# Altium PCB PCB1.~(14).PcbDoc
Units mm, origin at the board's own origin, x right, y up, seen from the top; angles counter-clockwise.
Board outline 149.35 x 57.4 mm, 2 copper layers (Top Layer, Bottom Layer); 100 components, 175 nets, 429 pads, 116 vias.
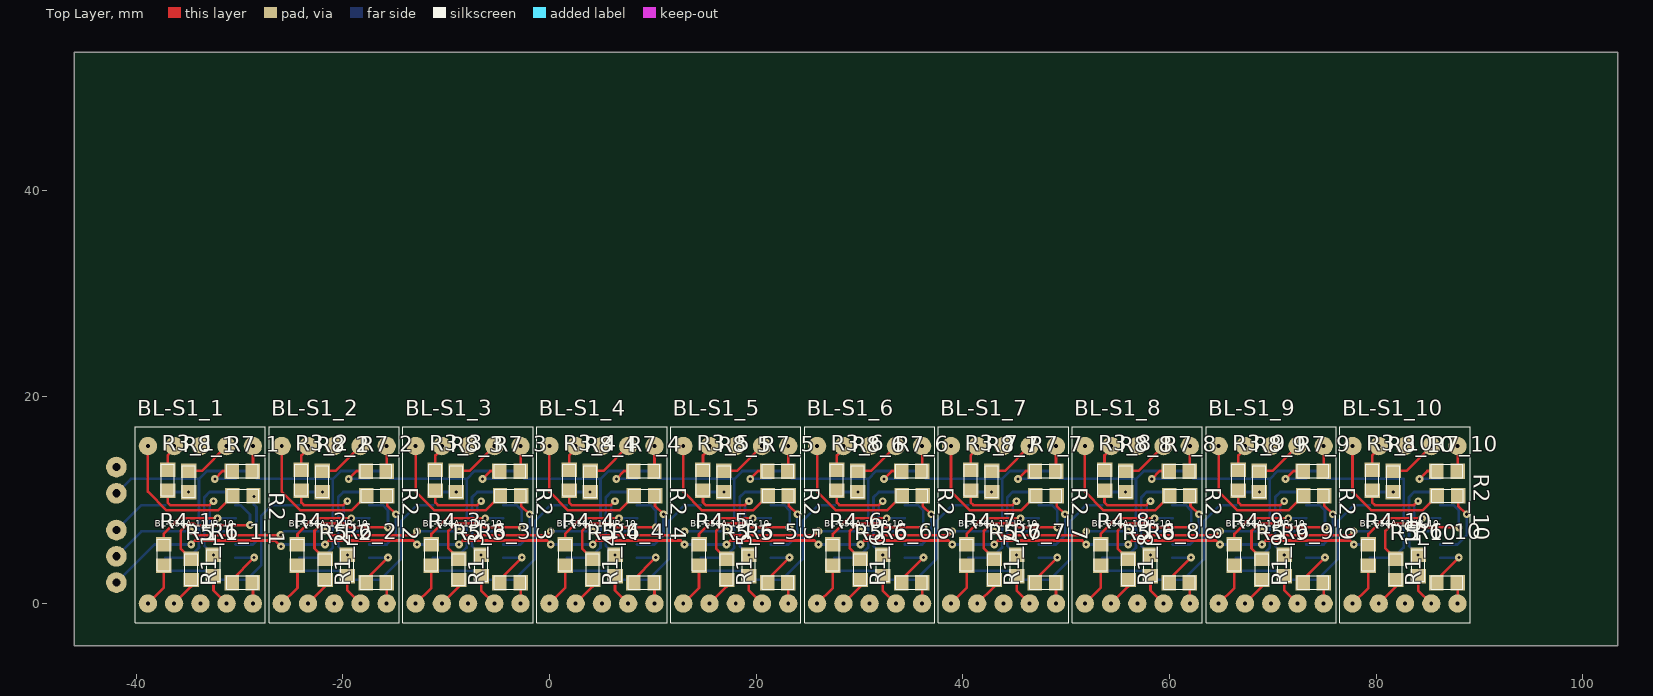
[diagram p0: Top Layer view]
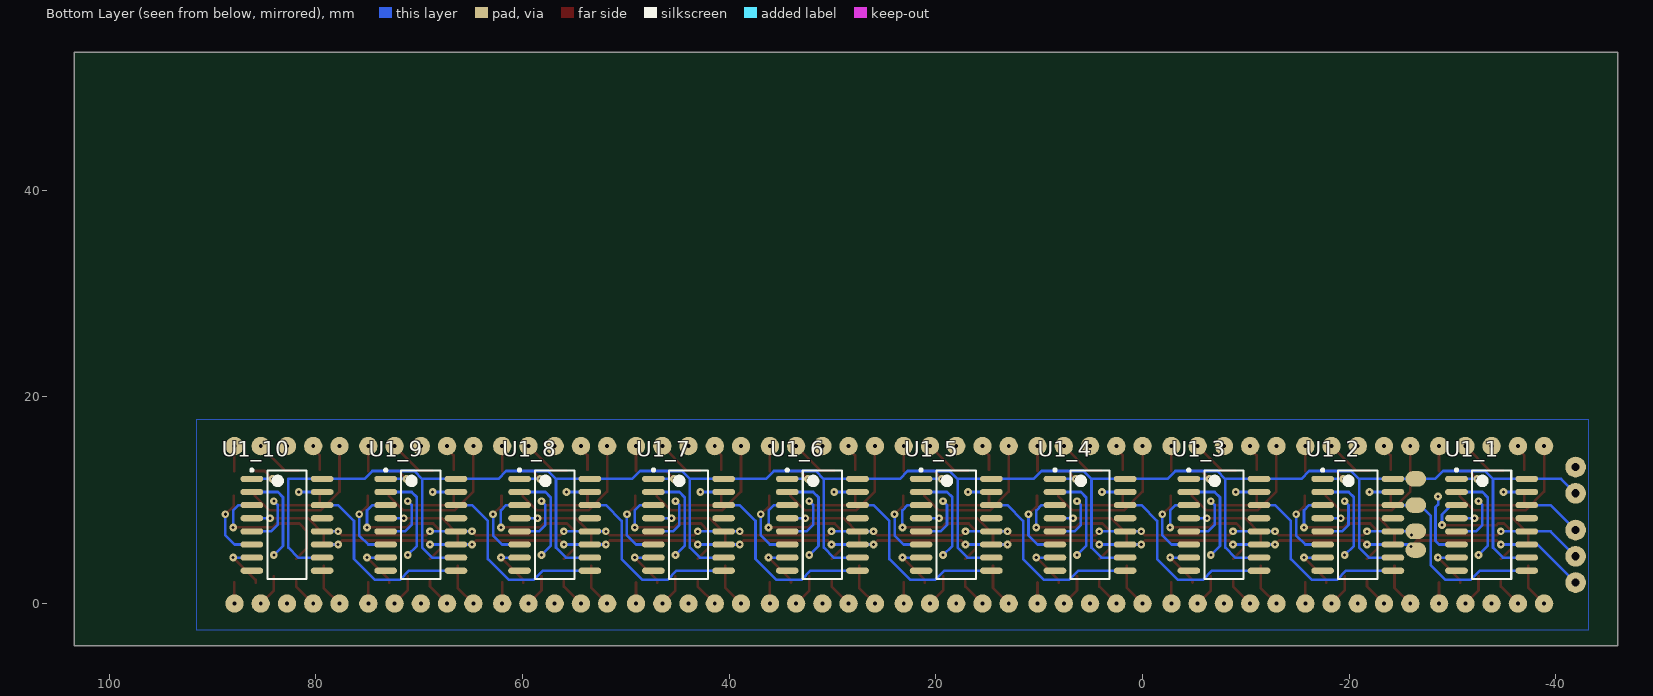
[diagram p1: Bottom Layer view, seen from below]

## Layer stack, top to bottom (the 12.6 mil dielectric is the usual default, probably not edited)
Top Solder: solder mask 0.0102, Solder Resist, Dk 3.5
Top Layer: signal copper 0.0356
Dielectric 1: dielectric 0.32, FR-4, Dk 4.8
Bottom Layer: signal copper 0.0356
Bottom Solder: solder mask 0.0102, Solder Resist, Dk 3.5

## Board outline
-45.974,-4.064 -45.974,53.34 103.378,53.34 103.378,-4.064 -5.588,-4.064

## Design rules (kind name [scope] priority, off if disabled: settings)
Clearance [All] p1: gap=0.127
MinimumSolderMaskSliver [All] p1 off: minsoldermaskwidth=0.254
PolygonConnect [All] p1: connectstyle=Relief reliefconductorwidth=0.254 reliefentries=4 polygonreliefangle="90 Angle" airgapwidth=0.381
RoomDefinition 10 [InComponentClass('10')] p1: confinementstyle=ConfineIn formatcopy=TRUE lockcomponents=FALSE outline 76.327,-2.54 91.44,-2.54 91.44,17.78 76.327,17.78
RoomDefinition 9 [InComponentClass('9')] p2: confinementstyle=ConfineIn formatcopy=TRUE lockcomponents=FALSE outline 63.373,-2.54 78.486,-2.54 78.486,17.78 63.373,17.78
RoomDefinition 8 [InComponentClass('8')] p3: confinementstyle=ConfineIn formatcopy=TRUE lockcomponents=FALSE outline 50.419,-2.54 65.532,-2.54 65.532,17.78 50.419,17.78
RoomDefinition 7 [InComponentClass('7')] p4: confinementstyle=ConfineIn formatcopy=TRUE lockcomponents=FALSE outline 37.465,-2.54 52.578,-2.54 52.578,17.78 37.465,17.78
RoomDefinition 6 [InComponentClass('6')] p5: confinementstyle=ConfineIn formatcopy=TRUE lockcomponents=FALSE outline 24.511,-2.54 39.624,-2.54 39.624,17.78 24.511,17.78
RoomDefinition 5 [InComponentClass('5')] p6: confinementstyle=ConfineIn formatcopy=TRUE lockcomponents=FALSE outline 11.557,-2.54 26.67,-2.54 26.67,17.78 11.557,17.78
RoomDefinition 4 [InComponentClass('4')] p7: confinementstyle=ConfineIn formatcopy=TRUE lockcomponents=FALSE outline -1.397,-2.54 13.716,-2.54 13.716,17.78 -1.397,17.78
RoomDefinition 2 [InComponentClass('2')] p8: confinementstyle=ConfineIn formatcopy=TRUE lockcomponents=FALSE outline -27.305,-2.54 -12.192,-2.54 -12.192,17.78 -27.305,17.78
RoomDefinition 1 [InComponentClass('1')] p9: confinementstyle=ConfineIn formatcopy=TRUE lockcomponents=FALSE outline -40.259,-2.54 -25.146,-2.54 -25.146,17.78 -40.259,17.78
RoomDefinition 3 [InComponentClass('3')] p10: confinementstyle=ConfineIn formatcopy=TRUE lockcomponents=FALSE outline -14.351,-2.54 0.762,-2.54 0.762,17.78 -14.351,17.78
RoutingVias [All] p1: holewidth=0.3 width=0.75 viastyle="Through Hole" minholewidth=0.3 minwidth=0.75 maxholewidth=0.711 maxwidth=1.778
SilkToBoardRegionClearance [All] p1 off:
SilkToSilkClearance [All] p1 off: silktosilkclearance=0.254
SilkToSolderMaskClearance [IsPad] p1 off: minsilkscreentomaskgap=0.254 clearancetoexposedcopper=TRUE
SolderMaskExpansion [All] p1: expansion=0.102
Width [All] p1: maxlimit=0.254 minlimit=0.2 preferedwidth=0.254
26 further rules are at their usual default settings.

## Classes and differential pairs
component class 6: BL-S1_6 R1_6 R2_6 R3_6 R4_6 R5_6 R6_6 R7_6 R8_6 U1_6
component class 5: BL-S1_5 R1_5 R2_5 R3_5 R4_5 R5_5 R6_5 R7_5 R8_5 U1_5
component class 1: BL-S1_1 R1_1 R2_1 R3_1 R4_1 R5_1 R6_1 R7_1 R8_1 U1_1
component class 2: BL-S1_2 R1_2 R2_2 R3_2 R4_2 R5_2 R6_2 R7_2 R8_2 U1_2
component class 3: BL-S1_3 R1_3 R2_3 R3_3 R4_3 R5_3 R6_3 R7_3 R8_3 U1_3
component class 4: BL-S1_4 R1_4 R2_4 R3_4 R4_4 R5_4 R6_4 R7_4 R8_4 U1_4
channel class Sheet2: 1 2 3 4 5 6 7 8 9 10
component class 7: BL-S1_7 R1_7 R2_7 R3_7 R4_7 R5_7 R6_7 R7_7 R8_7 U1_7
component class 8: BL-S1_8 R1_8 R2_8 R3_8 R4_8 R5_8 R6_8 R7_8 R8_8 U1_8
component class 9: BL-S1_9 R1_9 R2_9 R3_9 R4_9 R5_9 R6_9 R7_9 R8_9 U1_9
component class 10: BL-S1_10 R1_10 R2_10 R3_10 R4_10 R5_10 R6_10 R7_10 R8_10 U1_10

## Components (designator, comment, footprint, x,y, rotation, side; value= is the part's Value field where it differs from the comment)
BL-S1_1 "BL-S56A-11UR" BL-S56A-11UR -40.082,7.62 r0 top locked (schematic designator BL-S1)
BL-S1_2 "BL-S56A-11UR" BL-S56A-11UR -27.128,7.62 r0 top (schematic designator BL-S1)
BL-S1_3 "BL-S56A-11UR" BL-S56A-11UR -14.174,7.62 r0 top (schematic designator BL-S1)
BL-S1_4 "BL-S56A-11UR" BL-S56A-11UR -1.22,7.62 r0 top (schematic designator BL-S1)
BL-S1_5 "BL-S56A-11UR" BL-S56A-11UR 11.734,7.62 r0 top (schematic designator BL-S1)
BL-S1_6 "BL-S56A-11UR" BL-S56A-11UR 24.688,7.62 r0 top (schematic designator BL-S1)
BL-S1_7 "BL-S56A-11UR" BL-S56A-11UR 37.642,7.62 r0 top (schematic designator BL-S1)
BL-S1_8 "BL-S56A-11UR" BL-S56A-11UR 50.596,7.62 r0 top (schematic designator BL-S1)
BL-S1_9 "BL-S56A-11UR" BL-S56A-11UR 63.55,7.62 r0 top (schematic designator BL-S1)
BL-S1_10 "BL-S56A-11UR" BL-S56A-11UR 76.504,7.62 r0 top (schematic designator BL-S1)
R1_1 "310R" Res0805 -29.718,2.032 r180 top (schematic designator R1)
R1_2 "310R" Res0805 -16.764,2.032 r180 top (schematic designator R1)
R1_3 "310R" Res0805 -3.81,2.032 r180 top (schematic designator R1)
R1_4 "310R" Res0805 9.144,2.032 r180 top (schematic designator R1)
R1_5 "310R" Res0805 22.098,2.032 r180 top (schematic designator R1)
R1_6 "310R" Res0805 35.052,2.032 r180 top (schematic designator R1)
R1_7 "310R" Res0805 48.006,2.032 r180 top (schematic designator R1)
R1_8 "310R" Res0805 60.96,2.032 r180 top (schematic designator R1)
R1_9 "310R" Res0805 73.914,2.032 r180 top (schematic designator R1)
R1_10 "310R" Res0805 86.868,2.032 r180 top (schematic designator R1)
R2_1 "310R" Res0805 -29.666,10.414 r0 top (schematic designator R2)
R2_2 "310R" Res0805 -16.712,10.414 r0 top (schematic designator R2)
R2_3 "310R" Res0805 -3.758,10.414 r0 top (schematic designator R2)
R2_4 "310R" Res0805 9.196,10.414 r0 top (schematic designator R2)
R2_5 "310R" Res0805 22.15,10.414 r0 top (schematic designator R2)
R2_6 "310R" Res0805 35.104,10.414 r0 top (schematic designator R2)
R2_7 "310R" Res0805 48.058,10.414 r0 top (schematic designator R2)
R2_8 "310R" Res0805 61.012,10.414 r0 top (schematic designator R2)
R2_9 "310R" Res0805 73.966,10.414 r0 top (schematic designator R2)
R2_10 "310R" Res0805 86.92,10.414 r0 top (schematic designator R2)
R3_1 "310R" Res0805 -36.957,11.938 r270 top (schematic designator R3)
R3_2 "310R" Res0805 -24.003,11.938 r270 top (schematic designator R3)
R3_3 "310R" Res0805 -11.049,11.938 r270 top (schematic designator R3)
R3_4 "310R" Res0805 1.905,11.938 r270 top (schematic designator R3)
R3_5 "310R" Res0805 14.859,11.938 r270 top (schematic designator R3)
R3_6 "310R" Res0805 27.813,11.938 r270 top (schematic designator R3)
R3_7 "310R" Res0805 40.767,11.938 r270 top (schematic designator R3)
R3_8 "310R" Res0805 53.721,11.938 r270 top (schematic designator R3)
R3_9 "310R" Res0805 66.675,11.938 r270 top (schematic designator R3)
R3_10 "310R" Res0805 79.629,11.938 r270 top (schematic designator R3)
R4_1 "310R" Res0805 -37.338,4.699 r90 top (schematic designator R4)
R4_2 "310R" Res0805 -24.384,4.699 r90 top (schematic designator R4)
R4_3 "310R" Res0805 -11.43,4.699 r90 top (schematic designator R4)
R4_4 "310R" Res0805 1.524,4.699 r90 top (schematic designator R4)
R4_5 "310R" Res0805 14.478,4.699 r90 top (schematic designator R4)
R4_6 "310R" Res0805 27.432,4.699 r90 top (schematic designator R4)
R4_7 "310R" Res0805 40.386,4.699 r90 top (schematic designator R4)
R4_8 "310R" Res0805 53.34,4.699 r90 top (schematic designator R4)
R4_9 "310R" Res0805 66.294,4.699 r90 top (schematic designator R4)
R4_10 "310R" Res0805 79.248,4.699 r90 top (schematic designator R4)
R5_1 "310R" Res0805 -34.671,3.302 r90 top (schematic designator R5)
R5_2 "310R" Res0805 -21.717,3.302 r90 top (schematic designator R5)
R5_3 "310R" Res0805 -8.763,3.302 r90 top (schematic designator R5)
R5_4 "310R" Res0805 4.191,3.302 r90 top (schematic designator R5)
R5_5 "310R" Res0805 17.145,3.302 r90 top (schematic designator R5)
R5_6 "310R" Res0805 30.099,3.302 r90 top (schematic designator R5)
R5_7 "310R" Res0805 43.053,3.302 r90 top (schematic designator R5)
R5_8 "310R" Res0805 56.007,3.302 r90 top (schematic designator R5)
R5_9 "310R" Res0805 68.961,3.302 r90 top (schematic designator R5)
R5_10 "310R" Res0805 81.915,3.302 r90 top (schematic designator R5)
R6_1 "310R" Res0805 -32.512,3.683 r90 top (schematic designator R6)
R6_2 "310R" Res0805 -19.558,3.683 r90 top (schematic designator R6)
R6_3 "310R" Res0805 -6.604,3.683 r90 top (schematic designator R6)
R6_4 "310R" Res0805 6.35,3.683 r90 top (schematic designator R6)
R6_5 "310R" Res0805 19.304,3.683 r90 top (schematic designator R6)
R6_6 "310R" Res0805 32.258,3.683 r90 top (schematic designator R6)
R6_7 "310R" Res0805 45.212,3.683 r90 top (schematic designator R6)
R6_8 "310R" Res0805 58.166,3.683 r90 top (schematic designator R6)
R6_9 "310R" Res0805 71.12,3.683 r90 top (schematic designator R6)
R6_10 "310R" Res0805 84.074,3.683 r90 top (schematic designator R6)
R7_1 "310R" Res0805 -29.718,12.827 r180 top (schematic designator R7)
R7_2 "310R" Res0805 -16.764,12.827 r180 top (schematic designator R7)
R7_3 "310R" Res0805 -3.81,12.827 r180 top (schematic designator R7)
R7_4 "310R" Res0805 9.144,12.827 r180 top (schematic designator R7)
R7_5 "310R" Res0805 22.098,12.827 r180 top (schematic designator R7)
R7_6 "310R" Res0805 35.052,12.827 r180 top (schematic designator R7)
R7_7 "310R" Res0805 48.006,12.827 r180 top (schematic designator R7)
R7_8 "310R" Res0805 60.96,12.827 r180 top (schematic designator R7)
R7_9 "310R" Res0805 73.914,12.827 r180 top (schematic designator R7)
R7_10 "310R" Res0805 86.868,12.827 r180 top (schematic designator R7)
R8_1 "310R" Res0805 -34.925,11.811 r270 top (schematic designator R8)
R8_2 "310R" Res0805 -21.971,11.811 r270 top (schematic designator R8)
R8_3 "310R" Res0805 -9.017,11.811 r270 top (schematic designator R8)
R8_4 "310R" Res0805 3.937,11.811 r270 top (schematic designator R8)
R8_5 "310R" Res0805 16.891,11.811 r270 top (schematic designator R8)
R8_6 "310R" Res0805 29.845,11.811 r270 top (schematic designator R8)
R8_7 "310R" Res0805 42.799,11.811 r270 top (schematic designator R8)
R8_8 "310R" Res0805 55.753,11.811 r270 top (schematic designator R8)
R8_9 "310R" Res0805 68.707,11.811 r270 top (schematic designator R8)
R8_10 "310R" Res0805 81.661,11.811 r270 top (schematic designator R8)
U1_1 "HD74HC595FP" PRSP0016DH-B_N -33.782,7.62 r180 bottom (schematic designator U1)
U1_2 "HD74HC595FP" PRSP0016DH-B_N -20.828,7.62 r180 bottom (schematic designator U1)
U1_3 "HD74HC595FP" PRSP0016DH-B_N -7.874,7.62 r180 bottom (schematic designator U1)
U1_4 "HD74HC595FP" PRSP0016DH-B_N 5.08,7.62 r180 bottom (schematic designator U1)
U1_5 "HD74HC595FP" PRSP0016DH-B_N 18.034,7.62 r180 bottom (schematic designator U1)
U1_6 "HD74HC595FP" PRSP0016DH-B_N 30.988,7.62 r180 bottom (schematic designator U1)
U1_7 "HD74HC595FP" PRSP0016DH-B_N 43.942,7.62 r180 bottom (schematic designator U1)
U1_8 "HD74HC595FP" PRSP0016DH-B_N 56.896,7.62 r180 bottom (schematic designator U1)
U1_9 "HD74HC595FP" PRSP0016DH-B_N 69.85,7.62 r180 bottom (schematic designator U1)
U1_10 "HD74HC595FP" PRSP0016DH-B_N 82.804,7.62 r180 bottom (schematic designator U1)

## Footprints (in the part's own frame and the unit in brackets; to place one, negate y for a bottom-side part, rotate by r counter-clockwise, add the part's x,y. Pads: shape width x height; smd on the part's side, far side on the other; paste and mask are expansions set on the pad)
BL-S56A-11UR [mil]
  round 70 hole 15: 1(48.03,-300) 2(148.03,-300) 3(248.03,-300) 4(348.03,-300) 5(448.03,-300) 6(448.03,300) 7(348.03,300) 8(248.03,300) 9(148.03,300) 10(48.03,300)
  silkscreen extent 0,-374 496,374, body extent 0,-374 496,374, height 315
PRSP0016DH-B_N [mm] "SOP, 16-Leads, Body 10.06x5.5mm, Pitch 1.27mm, IPC Medium Density"
  oval 2.2x0.6 smd: 1(-3.4,4.445) 2(-3.4,3.175) 3(-3.4,1.905) 4(-3.4,0.635) 5(-3.4,-0.635) 6(-3.4,-1.905) 7(-3.4,-3.175) 8(-3.4,-4.445) 9(3.4,-4.445) 10(3.4,-3.175) 11(3.4,-1.905) 12(3.4,-0.635) 13(3.4,0.635) 14(3.4,1.905) 15(3.4,3.175) 16(3.4,4.445)
  silkscreen extent -3.52,-5.25 1.9,5.42, body extent -2.7,-5.25 2.7,5.25, height 2.2
Res0805 [mm]
  rect 1.4x1.5 smd: 1(-1.025,0) 2(1.025,0)
  silkscreen extent -1.52,-0.64 1.52,0.64, body extent -1.15,-0.67 1.15,0.68, height 0.76

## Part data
BL-S1_1 BL-S1_2 BL-S1_3 BL-S1_4 BL-S1_5 BL-S1_6 BL-S1_7 BL-S1_8 BL-S1_9 BL-S1_10: library part Component_1
R1_1 R1_2 R1_3 R1_4 R1_5 R1_6 R1_7 R1_8 R1_9 R1_10 R2_1 R2_2 R2_3 R2_4 R2_5 R2_6 R2_7 R2_8 R2_9 R2_10 R3_1 R3_2 R3_3 R3_4 R3_5 R3_6 R3_7 R3_8 R3_9 R3_10 R4_1 R4_2 R4_3 R4_4 R4_5 R4_6 R4_7 R4_8 R4_9 R4_10 R5_1 R5_2 R5_3 R5_4 R5_5 R5_6 R5_7 R5_8 R5_9 R5_10 R6_1 R6_2 R6_3 R6_4 R6_5 R6_6 R6_7 R6_8 R6_9 R6_10 R7_1 R7_2 R7_3 R7_4 R7_5 R7_6 R7_7 R7_8 R7_9 R7_10 R8_1 R8_2 R8_3 R8_4 R8_5 R8_6 R8_7 R8_8 R8_9 R8_10: library part Res1, "Resistor"
U1_1 U1_2 U1_3 U1_4 U1_5 U1_6 U1_7 U1_8 U1_9 U1_10: "8-bit Shift Register / Latch with 3-State Outputs"

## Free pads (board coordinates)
  round 2 hole 0.8: 2(-41.91,4.572) 3(-41.91,2.032) 4(-41.91,7.112) 5(-41.91,10.668) 6(-41.91,13.208)
  oval 2x1.5 smd far side: 8(-26.44,12.065) 9(-26.44,9.525) 10(-26.44,6.985) 11(-26.441,5.182)

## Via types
v1: diameter 0.75, hole 0.3, Top Layer to Bottom Layer, tented both sides, 94 vias
v2: diameter 0.75, hole 0.3, Top Layer to Bottom Layer, 22 vias

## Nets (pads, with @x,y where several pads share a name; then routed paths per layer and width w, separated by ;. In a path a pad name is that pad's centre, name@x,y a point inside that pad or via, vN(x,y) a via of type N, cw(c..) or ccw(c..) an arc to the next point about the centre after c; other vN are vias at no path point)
+5V: pad.5 pad.8 U1_1.10 U1_1.16 U1_2.10 U1_2.16 U1_3.10 U1_3.16 U1_4.10 U1_4.16 U1_5.10 U1_5.16 U1_6.10 U1_6.16 U1_7.10 U1_7.16 U1_8.10 U1_8.16 U1_9.10 U1_9.16 U1_10.10 U1_10.16 | length 234.1
  Bottom Layer w0.254: pad.5 -40.513,12.065 U1_1.16 -33.909,12.065 -33.147,12.827 -29.083,12.827 -28.321,12.065 U1_2.16 -20.955,12.065 -20.193,12.827 -16.129,12.827 -15.367,12.065 U1_3.16 -8.001,12.065 -7.239,12.827 -3.175,12.827 -2.413,12.065 U1_4.16 4.947,12.065 ; U1_1.10 -34.872,4.445 -33.915,5.402 -33.915,12.065 ; U1_2.10 -21.918,4.445 -20.961,5.402 -20.961,12.065 ; U1_3.10 -8.964,4.445 -8.007,5.402 -8.007,12.065 ; U1_4.10 3.99,4.445 4.947,5.402 4.947,12.065 ; U1_5.10 16.944,4.445 17.901,5.402 17.901,12.065 ; U1_6.10 29.898,4.445 30.855,5.402 30.855,12.065 ; U1_7.10 42.852,4.445 43.809,5.402 43.809,12.065 ; U1_8.10 55.806,4.445 56.763,5.402 56.763,12.065 ; U1_9.10 68.76,4.445 69.717,5.402 69.717,12.065 ; U1_10.10 81.714,4.445 82.671,5.402 82.671,12.065 ; 82.677,12.065 82.671,12.065 ; 4.947,12.065 4.953,12.065 5.715,12.827 9.779,12.827 10.541,12.065 U1_5.16 17.901,12.065 ; 17.901,12.065 17.907,12.065 18.669,12.827 22.733,12.827 23.495,12.065 U1_6.16 30.855,12.065 ; 30.855,12.065 30.861,12.065 31.623,12.827 35.687,12.827 36.449,12.065 U1_7.16 43.809,12.065 ; 43.809,12.065 43.815,12.065 44.577,12.827 48.641,12.827 49.403,12.065 U1_8.16 56.763,12.065 ; 56.763,12.065 56.769,12.065 57.531,12.827 61.595,12.827 62.357,12.065 U1_9.16 69.717,12.065 ; 69.717,12.065 69.723,12.065 70.485,12.827 74.549,12.827 75.311,12.065 U1_10.16 82.671,12.065
GND: BL-S1_1.3 BL-S1_1.8 BL-S1_2.3 BL-S1_2.8 BL-S1_3.3 BL-S1_3.8 BL-S1_4.3 BL-S1_4.8 BL-S1_5.3 BL-S1_5.8 BL-S1_6.3 BL-S1_6.8 BL-S1_7.3 BL-S1_7.8 BL-S1_8.3 BL-S1_8.8 BL-S1_9.3 BL-S1_9.8 BL-S1_10.3 BL-S1_10.8 pad.6 U1_1.8 U1_1.13 U1_2.8 U1_2.13 U1_3.8 U1_3.13 U1_4.8 U1_4.13 U1_5.8 U1_5.13 U1_6.8 U1_6.13 U1_7.8 U1_7.13 U1_8.8 U1_8.13 U1_9.8 U1_9.13 U1_10.8 U1_10.13
L_A_1: BL-S1_1.7 R8_1.1 | length 4.7
  Top Layer w0.254: R8_1.1 -33.646,12.836 BL-S1_1.7
L_A_2: BL-S1_2.7 R8_2.1 | length 4.7
  Top Layer w0.254: R8_2.1 -20.692,12.836 BL-S1_2.7
L_A_3: BL-S1_3.7 R8_3.1 | length 4.7
  Top Layer w0.254: R8_3.1 -7.738,12.836 BL-S1_3.7
L_A_4: BL-S1_4.7 R8_4.1 | length 4.7
  Top Layer w0.254: R8_4.1 5.216,12.836 BL-S1_4.7
L_A_5: BL-S1_5.7 R8_5.1 | length 4.7
  Top Layer w0.254: R8_5.1 18.17,12.836 BL-S1_5.7
L_A_6: BL-S1_6.7 R8_6.1 | length 9.4
  Top Layer w0.254: 31.124,12.836 R8_6.1 31.124,12.836 ; 31.124,12.836 BL-S1_6.7 31.124,12.836
L_A_7: BL-S1_7.7 R8_7.1 | length 4.7
  Top Layer w0.254: R8_7.1 44.078,12.836 BL-S1_7.7
L_A_8: BL-S1_8.7 R8_8.1 | length 4.7
  Top Layer w0.254: R8_8.1 57.032,12.836 BL-S1_8.7
L_A_9: BL-S1_9.7 R8_9.1 | length 4.7
  Top Layer w0.254: R8_9.1 69.986,12.836 BL-S1_9.7
L_A_10: BL-S1_10.7 R8_10.1 | length 4.7
  Top Layer w0.254: R8_10.1 82.94,12.836 BL-S1_10.7
L_B_1: BL-S1_1.6 R7_1.1 | length 2.4
  Top Layer w0.254: BL-S1_1.6 -28.693,15.231 R7_1.1
L_B_2: BL-S1_2.6 R7_2.1 | length 2.4
  Top Layer w0.254: BL-S1_2.6 -15.739,15.231 R7_2.1
L_B_3: BL-S1_3.6 R7_3.1 | length 2.4
  Top Layer w0.254: BL-S1_3.6 -2.785,15.231 R7_3.1
L_B_4: BL-S1_4.6 R7_4.1 | length 2.4
  Top Layer w0.254: BL-S1_4.6 10.169,15.231 R7_4.1
L_B_5: BL-S1_5.6 R7_5.1 | length 2.4
  Top Layer w0.254: BL-S1_5.6 23.123,15.231 R7_5.1
L_B_6: BL-S1_6.6 R7_6.1 | length 4.8
  Top Layer w0.254: BL-S1_6.6@36.077,15.231 R7_6.1 BL-S1_6.6@36.077,15.231 ; BL-S1_6.6@36.077,15.231 BL-S1_6.6 BL-S1_6.6@36.077,15.231
L_B_7: BL-S1_7.6 R7_7.1 | length 2.4
  Top Layer w0.254: BL-S1_7.6 49.031,15.231 R7_7.1
L_B_8: BL-S1_8.6 R7_8.1 | length 2.4
  Top Layer w0.254: BL-S1_8.6 61.985,15.231 R7_8.1
L_B_9: BL-S1_9.6 R7_9.1 | length 2.4
  Top Layer w0.254: BL-S1_9.6 74.939,15.231 R7_9.1
L_B_10: BL-S1_10.6 R7_10.1 | length 2.4
  Top Layer w0.254: BL-S1_10.6 87.893,15.231 R7_10.1
L_C_1: BL-S1_1.4 R6_1.1 | length 3.2
  Top Layer w0.254: R6_1.1 -32.512,1.27 BL-S1_1.4
L_C_2: BL-S1_2.4 R6_2.1 | length 3.2
  Top Layer w0.254: R6_2.1 -19.558,1.27 BL-S1_2.4
L_C_3: BL-S1_3.4 R6_3.1 | length 3.2
  Top Layer w0.254: R6_3.1 -6.604,1.27 BL-S1_3.4
L_C_4: BL-S1_4.4 R6_4.1 | length 3.2
  Top Layer w0.254: R6_4.1 6.35,1.27 BL-S1_4.4
L_C_5: BL-S1_5.4 R6_5.1 | length 3.2
  Top Layer w0.254: R6_5.1 19.304,1.27 BL-S1_5.4
L_C_6: BL-S1_6.4 R6_6.1 | length 6.4
  Top Layer w0.254: 32.258,1.27 R6_6.1 32.258,1.27 ; 32.258,1.27 BL-S1_6.4 32.258,1.27
L_C_7: BL-S1_7.4 R6_7.1 | length 3.2
  Top Layer w0.254: R6_7.1 45.212,1.27 BL-S1_7.4
L_C_8: BL-S1_8.4 R6_8.1 | length 3.2
  Top Layer w0.254: R6_8.1 58.166,1.27 BL-S1_8.4
L_C_9: BL-S1_9.4 R6_9.1 | length 3.2
  Top Layer w0.254: R6_9.1 71.12,1.27 BL-S1_9.4
L_C_10: BL-S1_10.4 R6_10.1 | length 3.2
  Top Layer w0.254: R6_10.1 84.074,1.27 BL-S1_10.4
L_D_1: BL-S1_1.2 R5_1.1 | length 2.8
  Top Layer w0.254: BL-S1_1.2 -34.671,1.651 R5_1.1@-34.671,2.15
L_D_2: BL-S1_2.2 R5_2.1 | length 2.8
  Top Layer w0.254: BL-S1_2.2 -21.717,1.651 R5_2.1@-21.717,2.15
L_D_3: BL-S1_3.2 R5_3.1 | length 2.8
  Top Layer w0.254: BL-S1_3.2 -8.763,1.651 R5_3.1@-8.763,2.15
L_D_4: BL-S1_4.2 R5_4.1 | length 2.8
  Top Layer w0.254: BL-S1_4.2 4.191,1.651 R5_4.1@4.191,2.15
L_D_5: BL-S1_5.2 R5_5.1 | length 2.8
  Top Layer w0.254: BL-S1_5.2 17.145,1.651 R5_5.1@17.145,2.15
L_D_6: BL-S1_6.2 R5_6.1 | length 5.7
  Top Layer w0.254: R5_6.1@30.099,1.651 BL-S1_6.2 R5_6.1@30.099,1.651 ; R5_6.1@30.099,1.651 30.099,2.15 R5_6.1@30.099,1.651
L_D_7: BL-S1_7.2 R5_7.1 | length 2.8
  Top Layer w0.254: BL-S1_7.2 43.053,1.651 R5_7.1@43.053,2.15
L_D_8: BL-S1_8.2 R5_8.1 | length 2.8
  Top Layer w0.254: BL-S1_8.2 56.007,1.651 R5_8.1@56.007,2.15
L_D_9: BL-S1_9.2 R5_9.1 | length 2.8
  Top Layer w0.254: BL-S1_9.2 68.961,1.651 R5_9.1@68.961,2.15
L_D_10: BL-S1_10.2 R5_10.1 | length 2.8
  Top Layer w0.254: BL-S1_10.2 81.915,1.651 R5_10.1@81.915,2.15
L_E_1: BL-S1_1.1 R4_1.1 | length 4.3
  Top Layer w0.254: BL-S1_1.1 -37.338,1.524 R4_1.1
L_E_2: BL-S1_2.1 R4_2.1 | length 4.3
  Top Layer w0.254: BL-S1_2.1 -24.384,1.524 R4_2.1
L_E_3: BL-S1_3.1 R4_3.1 | length 4.3
  Top Layer w0.254: BL-S1_3.1 -11.43,1.524 R4_3.1
L_E_4: BL-S1_4.1 R4_4.1 | length 4.3
  Top Layer w0.254: BL-S1_4.1 1.524,1.524 R4_4.1
L_E_5: BL-S1_5.1 R4_5.1 | length 4.3
  Top Layer w0.254: BL-S1_5.1 14.478,1.524 R4_5.1
L_E_6: BL-S1_6.1 R4_6.1 | length 8.6
  Top Layer w0.254: 27.432,1.524 BL-S1_6.1 27.432,1.524 ; 27.432,1.524 R4_6.1 27.432,1.524
L_E_7: BL-S1_7.1 R4_7.1 | length 4.3
  Top Layer w0.254: BL-S1_7.1 40.386,1.524 R4_7.1
L_E_8: BL-S1_8.1 R4_8.1 | length 4.3
  Top Layer w0.254: BL-S1_8.1 53.34,1.524 R4_8.1
L_E_9: BL-S1_9.1 R4_9.1 | length 4.3
  Top Layer w0.254: BL-S1_9.1 66.294,1.524 R4_9.1
L_E_10: BL-S1_10.1 R4_10.1 | length 4.3
  Top Layer w0.254: BL-S1_10.1 79.248,1.524 R4_10.1
L_F_1: BL-S1_1.9 R3_1.1 | length 2.5
  Top Layer w0.254: R3_1.1 -36.957,14.351 -36.322,14.986 BL-S1_1.9
L_F_2: BL-S1_2.9 R3_2.1 | length 2.5
  Top Layer w0.254: R3_2.1 -24.003,14.351 -23.368,14.986 BL-S1_2.9
L_F_3: BL-S1_3.9 R3_3.1 | length 2.5
  Top Layer w0.254: R3_3.1 -11.049,14.351 -10.414,14.986 BL-S1_3.9
L_F_4: BL-S1_4.9 R3_4.1 | length 2.5
  Top Layer w0.254: R3_4.1 1.905,14.351 2.54,14.986 BL-S1_4.9
L_F_5: BL-S1_5.9 R3_5.1 | length 2.5
  Top Layer w0.254: R3_5.1 14.859,14.351 15.494,14.986 BL-S1_5.9
L_F_6: BL-S1_6.9 R3_6.1 | length 5.1
  Top Layer w0.254: 27.813,14.351 R3_6.1 27.813,14.351 ; 27.813,14.351 BL-S1_6.9@28.448,14.986 ; 27.813,14.351 BL-S1_6.9@28.448,14.986 ; BL-S1_6.9@28.448,14.986 BL-S1_6.9 BL-S1_6.9@28.448,14.986
L_F_7: BL-S1_7.9 R3_7.1 | length 2.5
  Top Layer w0.254: R3_7.1 40.767,14.351 41.402,14.986 BL-S1_7.9
L_F_8: BL-S1_8.9 R3_8.1 | length 2.5
  Top Layer w0.254: R3_8.1 53.721,14.351 54.356,14.986 BL-S1_8.9
L_F_9: BL-S1_9.9 R3_9.1 | length 2.5
  Top Layer w0.254: R3_9.1 66.675,14.351 67.31,14.986 BL-S1_9.9
L_F_10: BL-S1_10.9 R3_10.1 | length 2.5
  Top Layer w0.254: R3_10.1 79.629,14.351 80.264,14.986 BL-S1_10.9
L_G_1: BL-S1_1.10 R2_1.1 | length 13.9
  Top Layer w0.254: BL-S1_1.10 -38.862,10.829 -37.044,9.011 -32.094,9.011 R2_1.1
L_G_2: BL-S1_2.10 R2_2.1 | length 13.9
  Top Layer w0.254: BL-S1_2.10 -25.908,10.829 -24.09,9.011 -19.14,9.011 R2_2.1
L_G_3: BL-S1_3.10 R2_3.1 | length 13.9
  Top Layer w0.254: BL-S1_3.10 -12.954,10.829 -11.136,9.011 -6.186,9.011 R2_3.1
L_G_4: BL-S1_4.10 R2_4.1 | length 13.9
  Top Layer w0.254: BL-S1_4.10 0,10.829 1.818,9.011 6.768,9.011 R2_4.1
L_G_5: BL-S1_5.10 R2_5.1 | length 13.9
  Top Layer w0.254: BL-S1_5.10 12.954,10.829 14.772,9.011 19.722,9.011 R2_5.1
L_G_6: BL-S1_6.10 R2_6.1 | length 27.8
  Top Layer w0.254: 25.908,10.829 27.726,9.011 ; 25.908,10.829 BL-S1_6.10 25.908,10.829 ; 25.908,10.829 27.726,9.011 ; 27.726,9.011 32.676,9.011 ; 27.726,9.011 32.676,9.011 ; 32.676,9.011 R2_6.1 32.676,9.011
L_G_7: BL-S1_7.10 R2_7.1 | length 13.9
  Top Layer w0.254: BL-S1_7.10 38.862,10.829 40.68,9.011 45.63,9.011 R2_7.1
L_G_8: BL-S1_8.10 R2_8.1 | length 13.9
  Top Layer w0.254: BL-S1_8.10 51.816,10.829 53.634,9.011 58.584,9.011 R2_8.1
L_G_9: BL-S1_9.10 R2_9.1 | length 13.9
  Top Layer w0.254: BL-S1_9.10 64.77,10.829 66.588,9.011 71.538,9.011 R2_9.1
L_G_10: BL-S1_10.10 R2_10.1 | length 13.9
  Top Layer w0.254: BL-S1_10.10 77.724,10.829 79.542,9.011 84.492,9.011 R2_10.1
L_H_1: BL-S1_1.5 R1_1.1 | length 2
  Top Layer w0.254: BL-S1_1.5 -28.693,0.009 R1_1.1
L_H_2: BL-S1_2.5 R1_2.1 | length 2
  Top Layer w0.254: BL-S1_2.5 -15.739,0.009 R1_2.1
L_H_3: BL-S1_3.5 R1_3.1 | length 2
  Top Layer w0.254: BL-S1_3.5 -2.785,0.009 R1_3.1
L_H_4: BL-S1_4.5 R1_4.1 | length 2
  Top Layer w0.254: BL-S1_4.5 10.169,0.009 R1_4.1
L_H_5: BL-S1_5.5 R1_5.1 | length 2
  Top Layer w0.254: BL-S1_5.5 23.123,0.009 R1_5.1
L_H_6: BL-S1_6.5 R1_6.1 | length 4.1
  Top Layer w0.254: BL-S1_6.5@36.077,0.009 BL-S1_6.5 BL-S1_6.5@36.077,0.009 ; BL-S1_6.5@36.077,0.009 R1_6.1 BL-S1_6.5@36.077,0.009
L_H_7: BL-S1_7.5 R1_7.1 | length 2
  Top Layer w0.254: BL-S1_7.5 49.031,0.009 R1_7.1
L_H_8: BL-S1_8.5 R1_8.1 | length 2
  Top Layer w0.254: BL-S1_8.5 61.985,0.009 R1_8.1
L_H_9: BL-S1_9.5 R1_9.1 | length 2
  Top Layer w0.254: BL-S1_9.5 74.939,0.009 R1_9.1
L_H_10: BL-S1_10.5 R1_10.1 | length 2
  Top Layer w0.254: BL-S1_10.5 87.893,0.009 R1_10.1
NetR1_1_2: R1_1.2 U1_1.7 | length 5.1
  Top Layer w0.254: R1_1.2 -30.743,2.277 v1(-28.575,4.445)
  Bottom Layer w0.254: U1_1.7 v1(-28.575,4.445)
NetR1_2_2: R1_2.2 U1_2.7 | length 5.1
  Top Layer w0.254: R1_2.2 -17.789,2.277 v1(-15.621,4.445)
  Bottom Layer w0.254: U1_2.7 v1(-15.621,4.445)
NetR1_3_2: R1_3.2 U1_3.7 | length 5.1
  Top Layer w0.254: R1_3.2 -4.835,2.277 v1(-2.667,4.445)
  Bottom Layer w0.254: U1_3.7 v1(-2.667,4.445)
NetR1_4_2: R1_4.2 U1_4.7 | length 5.1
  Top Layer w0.254: R1_4.2 8.119,2.277 v1(10.287,4.445)
  Bottom Layer w0.254: U1_4.7 v1(10.287,4.445)
NetR1_5_2: R1_5.2 U1_5.7 | length 5.1
  Top Layer w0.254: R1_5.2 21.073,2.277 v1(23.241,4.445)
  Bottom Layer w0.254: U1_5.7 v1(23.241,4.445)
NetR1_6_2: R1_6.2 U1_6.7 | length 10.2
  Top Layer w0.254: R1_6.2@34.027,2.277 v1(36.195,4.445) R1_6.2@34.027,2.277 ; R1_6.2@34.027,2.277 R1_6.2 R1_6.2@34.027,2.277
  Bottom Layer w0.254: U1_6.7 v1(36.195,4.445) U1_6.7
NetR1_7_2: R1_7.2 U1_7.7 | length 5.1
  Top Layer w0.254: R1_7.2 46.981,2.277 v1(49.149,4.445)
  Bottom Layer w0.254: U1_7.7 v1(49.149,4.445)
NetR1_8_2: R1_8.2 U1_8.7 | length 5.1
  Top Layer w0.254: R1_8.2 59.935,2.277 v1(62.103,4.445)
  Bottom Layer w0.254: U1_8.7 v1(62.103,4.445)
NetR1_9_2: R1_9.2 U1_9.7 | length 5.1
  Top Layer w0.254: R1_9.2 72.889,2.277 v1(75.057,4.445)
  Bottom Layer w0.254: U1_9.7 v1(75.057,4.445)
NetR1_10_2: R1_10.2 U1_10.7 | length 5.1
  Top Layer w0.254: R1_10.2 85.843,2.277 v1(88.011,4.445)
  Bottom Layer w0.254: U1_10.7 v1(88.011,4.445)
NetR2_1_2: R2_1.2 U1_1.6 | length 6.6
  Bottom Layer w0.254: U1_1.6 -28.702,5.715 -28.352,6.065 -28.352,9.333 -28.6,9.581 v1(-28.6,10.363)
NetR2_2_2: R2_2.2 U1_2.6 | length 7.1
  Top Layer w0.254: R2_2.2 -15.687,9.464 v1(-14.865,8.642)
  Bottom Layer w0.254: U1_2.6 -15.748,5.715 -14.865,6.598 v1(-14.865,8.642)
NetR2_3_2: R2_3.2 U1_3.6 | length 7.1
  Top Layer w0.254: R2_3.2 -2.733,9.464 v1(-1.911,8.642)
  Bottom Layer w0.254: U1_3.6 -2.794,5.715 -1.911,6.598 v1(-1.911,8.642)
NetR2_4_2: R2_4.2 U1_4.6 | length 7.1
  Top Layer w0.254: R2_4.2 10.221,9.464 v1(11.043,8.642)
  Bottom Layer w0.254: U1_4.6 10.16,5.715 11.043,6.598 v1(11.043,8.642)
NetR2_5_2: R2_5.2 U1_5.6 | length 7.1
  Top Layer w0.254: R2_5.2 23.175,9.464 v1(23.997,8.642)
  Bottom Layer w0.254: U1_5.6 23.114,5.715 23.997,6.598 v1(23.997,8.642)
NetR2_6_2: R2_6.2 U1_6.6 | length 14.2
  Top Layer w0.254: 36.129,9.464 R2_6.2 36.129,9.464 ; 36.129,9.464 v1(36.951,8.642) 36.129,9.464
  Bottom Layer w0.254: 36.068,5.715 U1_6.6 36.068,5.715 ; 36.068,5.715 36.951,6.598 ; 36.068,5.715 36.951,6.598 ; 36.951,6.598 v1(36.951,8.642) 36.951,6.598
NetR2_7_2: R2_7.2 U1_7.6 | length 7.1
  Top Layer w0.254: R2_7.2 49.083,9.464 v1(49.905,8.642)
  Bottom Layer w0.254: U1_7.6 49.022,5.715 49.905,6.598 v1(49.905,8.642)
NetR2_8_2: R2_8.2 U1_8.6 | length 7.1
  Top Layer w0.254: R2_8.2 62.037,9.464 v1(62.859,8.642)
  Bottom Layer w0.254: U1_8.6 61.976,5.715 62.859,6.598 v1(62.859,8.642)
NetR2_9_2: R2_9.2 U1_9.6 | length 7.1
  Top Layer w0.254: R2_9.2 74.991,9.464 v1(75.813,8.642)
  Bottom Layer w0.254: U1_9.6 74.93,5.715 75.813,6.598 v1(75.813,8.642)
NetR2_10_2: R2_10.2 U1_10.6 | length 7.1
  Top Layer w0.254: R2_10.2 87.945,9.464 v1(88.767,8.642)
  Bottom Layer w0.254: U1_10.6 87.884,5.715 88.767,6.598 v1(88.767,8.642)
NetR3_1_2: R3_1.2 U1_1.5 | length 11.1
  Top Layer w0.254: R3_1.2 -36.957,9.779 -36.703,9.525 -32.893,9.525 v1(-32.512,9.906)
  Bottom Layer w0.254: v1(-32.512,9.906) -32.887,9.531 -32.887,7.614 -32.258,6.985 U1_1.5
NetR3_2_2: R3_2.2 U1_2.5 | length 11.1
  Top Layer w0.254: R3_2.2 -24.003,9.779 -23.749,9.525 -19.939,9.525 v1(-19.558,9.906)
  Bottom Layer w0.254: v1(-19.558,9.906) -19.933,9.531 -19.933,7.614 -19.304,6.985 U1_2.5
NetR3_3_2: R3_3.2 U1_3.5 | length 11.1
  Top Layer w0.254: R3_3.2 -11.049,9.779 -10.795,9.525 -6.985,9.525 v1(-6.604,9.906)
  Bottom Layer w0.254: v1(-6.604,9.906) -6.979,9.531 -6.979,7.614 -6.35,6.985 U1_3.5
NetR3_4_2: R3_4.2 U1_4.5 | length 11.1
  Top Layer w0.254: R3_4.2 1.905,9.779 2.159,9.525 5.969,9.525 v1(6.35,9.906)
  Bottom Layer w0.254: v1(6.35,9.906) 5.975,9.531 5.975,7.614 6.604,6.985 U1_4.5
NetR3_5_2: R3_5.2 U1_5.5 | length 11.1
  Top Layer w0.254: R3_5.2 14.859,9.779 15.113,9.525 18.923,9.525 v1(19.304,9.906)
  Bottom Layer w0.254: v1(19.304,9.906) 18.929,9.531 18.929,7.614 19.558,6.985 U1_5.5
NetR3_6_2: R3_6.2 U1_6.5 | length 22.1
  Top Layer w0.254: 27.813,9.779 R3_6.2 27.813,9.779 ; 27.813,9.779 28.067,9.525 ; 27.813,9.779 28.067,9.525 ; 28.067,9.525 31.877,9.525 ; 28.067,9.525 31.877,9.525 ; 31.877,9.525 v1(32.258,9.906) 31.877,9.525
  Bottom Layer w0.254: 31.883,7.614 32.512,6.985 ; 31.883,7.614 31.883,9.531 ; 31.883,7.614 32.512,6.985 ; 31.883,7.614 31.883,9.531 ; 31.883,9.531 v1(32.258,9.906) 31.883,9.531 ; 32.512,6.985 U1_6.5 32.512,6.985
NetR3_7_2: R3_7.2 U1_7.5 | length 11.1
  Top Layer w0.254: R3_7.2 40.767,9.779 41.021,9.525 44.831,9.525 v1(45.212,9.906)
  Bottom Layer w0.254: v1(45.212,9.906) 44.837,9.531 44.837,7.614 45.466,6.985 U1_7.5
NetR3_8_2: R3_8.2 U1_8.5 | length 11.1
  Top Layer w0.254: R3_8.2 53.721,9.779 53.975,9.525 57.785,9.525 v1(58.166,9.906)
  Bottom Layer w0.254: v1(58.166,9.906) 57.791,9.531 57.791,7.614 58.42,6.985 U1_8.5
NetR3_9_2: R3_9.2 U1_9.5 | length 11.1
  Top Layer w0.254: R3_9.2 66.675,9.779 66.929,9.525 70.739,9.525 v1(71.12,9.906)
  Bottom Layer w0.254: v1(71.12,9.906) 70.745,9.531 70.745,7.614 71.374,6.985 U1_9.5
NetR3_10_2: R3_10.2 U1_10.5 | length 11.1
  Top Layer w0.254: R3_10.2 79.629,9.779 79.883,9.525 83.693,9.525 v1(84.074,9.906)
  Bottom Layer w0.254: v1(84.074,9.906) 83.699,9.531 83.699,7.614 84.328,6.985 U1_10.5
NetR4_1_2: R4_1.2 U1_1.4 | length 8.6
  Top Layer w0.254: R4_1.2 -37.338,6.731 -35.814,8.255 v1(-32.131,8.255)
  Bottom Layer w0.254: v1(-32.131,8.255) U1_1.4
NetR4_2_2: R4_2.2 U1_2.4 | length 8.6
  Top Layer w0.254: R4_2.2 -24.384,6.731 -22.86,8.255 v1(-19.177,8.255)
  Bottom Layer w0.254: v1(-19.177,8.255) U1_2.4
NetR4_3_2: R4_3.2 U1_3.4 | length 8.6
  Top Layer w0.254: R4_3.2 -11.43,6.731 -9.906,8.255 v1(-6.223,8.255)
  Bottom Layer w0.254: v1(-6.223,8.255) U1_3.4
NetR4_4_2: R4_4.2 U1_4.4 | length 8.6
  Top Layer w0.254: R4_4.2 1.524,6.731 3.048,8.255 v1(6.731,8.255)
  Bottom Layer w0.254: v1(6.731,8.255) U1_4.4
NetR4_5_2: R4_5.2 U1_5.4 | length 8.6
  Top Layer w0.254: R4_5.2 14.478,6.731 16.002,8.255 v1(19.685,8.255)
  Bottom Layer w0.254: v1(19.685,8.255) U1_5.4
NetR4_6_2: R4_6.2 U1_6.4 | length 17.2
  Top Layer w0.254: 27.432,6.731 R4_6.2 27.432,6.731 ; 27.432,6.731 28.956,8.255 ; 27.432,6.731 28.956,8.255 ; 28.956,8.255 v1(32.639,8.255) 28.956,8.255
  Bottom Layer w0.254: v1(32.639,8.255) U1_6.4 v1(32.639,8.255)
NetR4_7_2: R4_7.2 U1_7.4 | length 8.6
  Top Layer w0.254: R4_7.2 40.386,6.731 41.91,8.255 v1(45.593,8.255)
  Bottom Layer w0.254: v1(45.593,8.255) U1_7.4
NetR4_8_2: R4_8.2 U1_8.4 | length 8.6
  Top Layer w0.254: R4_8.2 53.34,6.731 54.864,8.255 v1(58.547,8.255)
  Bottom Layer w0.254: v1(58.547,8.255) U1_8.4
NetR4_9_2: R4_9.2 U1_9.4 | length 8.6
  Top Layer w0.254: R4_9.2 66.294,6.731 67.818,8.255 v1(71.501,8.255)
  Bottom Layer w0.254: v1(71.501,8.255) U1_9.4
NetR4_10_2: R4_10.2 U1_10.4 | length 8.6
  Top Layer w0.254: R4_10.2 79.248,6.731 80.772,8.255 v1(84.455,8.255)
  Bottom Layer w0.254: v1(84.455,8.255) U1_10.4
NetR5_1_2: R5_1.2 U1_1.3 | length 13
  Top Layer w0.254: R5_1.2 -35.687,5.343 -35.687,7.038 -34.978,7.747 -34.417,7.747 -34.265,7.595 v1(-28.981,7.595)
  Bottom Layer w0.254: U1_1.3 -29.896,9.525 -28.981,8.611 v1(-28.981,7.595)
NetR5_2_2: R5_2.2 U1_2.3 | length 14.4
  Top Layer w0.254: R5_2.2 -22.733,5.343 -22.733,7.038 -22.024,7.747 -19.812,7.747 -19.431,7.366 v1(-15.621,7.366)
  Bottom Layer w0.254: U1_2.3 -16.129,9.525 -15.621,9.017 v1(-15.621,7.366)
NetR5_3_2: R5_3.2 U1_3.3 | length 14.4
  Top Layer w0.254: R5_3.2 -9.779,5.343 -9.779,7.038 -9.07,7.747 -6.858,7.747 -6.477,7.366 v1(-2.667,7.366)
  Bottom Layer w0.254: U1_3.3 -3.175,9.525 -2.667,9.017 v1(-2.667,7.366)
NetR5_4_2: R5_4.2 U1_4.3 | length 14.4
  Top Layer w0.254: R5_4.2 3.175,5.343 3.175,7.038 3.884,7.747 6.096,7.747 6.477,7.366 v1(10.287,7.366)
  Bottom Layer w0.254: U1_4.3 9.779,9.525 10.287,9.017 v1(10.287,7.366)
NetR5_5_2: R5_5.2 U1_5.3 | length 14.4
  Top Layer w0.254: R5_5.2 16.129,5.343 16.129,7.038 16.838,7.747 19.05,7.747 19.431,7.366 v1(23.241,7.366)
  Bottom Layer w0.254: U1_5.3 22.733,9.525 23.241,9.017 v1(23.241,7.366)
NetR5_6_2: R5_6.2 U1_6.3 | length 28.7
  Top Layer w0.254: 29.083,5.343 29.083,7.038 ; 29.083,5.343 R5_6.2 29.083,5.343 ; 29.083,5.343 29.083,7.038 ; 29.083,7.038 29.792,7.747 ; 29.083,7.038 29.792,7.747 ; 29.792,7.747 32.004,7.747 ; 29.792,7.747 32.004,7.747 ; 32.004,7.747 32.385,7.366 ; 32.004,7.747 32.385,7.366 ; 32.385,7.366 v1(36.195,7.366) 32.385,7.366
  Bottom Layer w0.254: 35.687,9.525 36.195,9.017 ; 35.687,9.525 U1_6.3 35.687,9.525 ; 35.687,9.525 36.195,9.017 ; 36.195,9.017 v1(36.195,7.366) 36.195,9.017
NetR5_7_2: R5_7.2 U1_7.3 | length 14.4
  Top Layer w0.254: R5_7.2 42.037,5.343 42.037,7.038 42.746,7.747 44.958,7.747 45.339,7.366 v1(49.149,7.366)
  Bottom Layer w0.254: U1_7.3 48.641,9.525 49.149,9.017 v1(49.149,7.366)
NetR5_8_2: R5_8.2 U1_8.3 | length 14.4
  Top Layer w0.254: R5_8.2 54.991,5.343 54.991,7.038 55.7,7.747 57.912,7.747 58.293,7.366 v1(62.103,7.366)
  Bottom Layer w0.254: U1_8.3 61.595,9.525 62.103,9.017 v1(62.103,7.366)
NetR5_9_2: R5_9.2 U1_9.3 | length 14.4
  Top Layer w0.254: R5_9.2 67.945,5.343 67.945,7.038 68.654,7.747 70.866,7.747 71.247,7.366 v1(75.057,7.366)
  Bottom Layer w0.254: U1_9.3 74.549,9.525 75.057,9.017 v1(75.057,7.366)
NetR5_10_2: R5_10.2 U1_10.3 | length 14.4
  Top Layer w0.254: R5_10.2 80.899,5.343 80.899,7.038 81.608,7.747 83.82,7.747 84.201,7.366 v1(88.011,7.366)
  Bottom Layer w0.254: U1_10.3 87.503,9.525 88.011,9.017 v1(88.011,7.366)
NetR6_1_2: R6_1.2 U1_1.2 | length 9.2
  Top Layer w0.254: v2(-32.512,4.699) R6_1.2
  Bottom Layer w0.254: v2(-32.512,4.699) -33.401,5.588 -33.401,10.287 -32.893,10.795 U1_1.2
NetR6_2_2: R6_2.2 U1_2.2 | length 9.2
  Top Layer w0.254: v2(-19.558,4.699) R6_2.2
  Bottom Layer w0.254: v2(-19.558,4.699) -20.447,5.588 -20.447,10.287 -19.939,10.795 U1_2.2
NetR6_3_2: R6_3.2 U1_3.2 | length 9.2
  Top Layer w0.254: v2(-6.604,4.699) R6_3.2
  Bottom Layer w0.254: v2(-6.604,4.699) -7.493,5.588 -7.493,10.287 -6.985,10.795 U1_3.2
NetR6_4_2: R6_4.2 U1_4.2 | length 9.2
  Top Layer w0.254: v2(6.35,4.699) R6_4.2
  Bottom Layer w0.254: v2(6.35,4.699) 5.461,5.588 5.461,10.287 5.969,10.795 U1_4.2
NetR6_5_2: R6_5.2 U1_5.2 | length 9.2
  Top Layer w0.254: v2(19.304,4.699) R6_5.2
  Bottom Layer w0.254: v2(19.304,4.699) 18.415,5.588 18.415,10.287 18.923,10.795 U1_5.2
NetR6_6_2: R6_6.2 U1_6.2 | length 18.4
  Top Layer w0.254: v2(32.258,4.699) R6_6.2 v2(32.258,4.699)
  Bottom Layer w0.254: 31.369,5.588 v2(32.258,4.699) 31.369,5.588 ; 31.369,5.588 31.369,10.287 ; 31.369,5.588 31.369,10.287 ; 31.369,10.287 31.877,10.795 ; 31.369,10.287 31.877,10.795 ; 31.877,10.795 U1_6.2 31.877,10.795
NetR6_7_2: R6_7.2 U1_7.2 | length 9.2
  Top Layer w0.254: v2(45.212,4.699) R6_7.2
  Bottom Layer w0.254: v2(45.212,4.699) 44.323,5.588 44.323,10.287 44.831,10.795 U1_7.2
NetR6_8_2: R6_8.2 U1_8.2 | length 9.2
  Top Layer w0.254: v2(58.166,4.699) R6_8.2
  Bottom Layer w0.254: v2(58.166,4.699) 57.277,5.588 57.277,10.287 57.785,10.795 U1_8.2
NetR6_9_2: R6_9.2 U1_9.2 | length 9.2
  Top Layer w0.254: v2(71.12,4.699) R6_9.2
  Bottom Layer w0.254: v2(71.12,4.699) 70.231,5.588 70.231,10.287 70.739,10.795 U1_9.2
NetR6_10_2: R6_10.2 U1_10.2 | length 9.2
  Top Layer w0.254: v2(84.074,4.699) R6_10.2
  Bottom Layer w0.254: v2(84.074,4.699) 83.185,5.588 83.185,10.287 83.693,10.795 U1_10.2
NetR7_1_2: R7_1.2 U1_1.1 | length 4
  Top Layer w0.254: v1(-32.385,12.065) -31.623,12.827 R7_1.2
  Bottom Layer w0.254: v1(-32.385,12.065) U1_1.1
NetR7_2_2: R7_2.2 U1_2.1 | length 4
  Top Layer w0.254: v1(-19.431,12.065) -18.669,12.827 R7_2.2
  Bottom Layer w0.254: v1(-19.431,12.065) U1_2.1
NetR7_3_2: R7_3.2 U1_3.1 | length 4
  Top Layer w0.254: v1(-6.477,12.065) -5.715,12.827 R7_3.2
  Bottom Layer w0.254: v1(-6.477,12.065) U1_3.1
NetR7_4_2: R7_4.2 U1_4.1 | length 4
  Top Layer w0.254: v1(6.477,12.065) 7.239,12.827 R7_4.2
  Bottom Layer w0.254: v1(6.477,12.065) U1_4.1
NetR7_5_2: R7_5.2 U1_5.1 | length 4
  Top Layer w0.254: v1(19.431,12.065) 20.193,12.827 R7_5.2
  Bottom Layer w0.254: v1(19.431,12.065) U1_5.1
NetR7_6_2: R7_6.2 U1_6.1 | length 7.9
  Top Layer w0.254: 33.147,12.827 v1(32.385,12.065) 33.147,12.827 ; 33.147,12.827 R7_6.2 33.147,12.827
  Bottom Layer w0.254: v1(32.385,12.065) U1_6.1 v1(32.385,12.065)
NetR7_7_2: R7_7.2 U1_7.1 | length 4
  Top Layer w0.254: v1(45.339,12.065) 46.101,12.827 R7_7.2
  Bottom Layer w0.254: v1(45.339,12.065) U1_7.1
NetR7_8_2: R7_8.2 U1_8.1 | length 4
  Top Layer w0.254: v1(58.293,12.065) 59.055,12.827 R7_8.2
  Bottom Layer w0.254: v1(58.293,12.065) U1_8.1
NetR7_9_2: R7_9.2 U1_9.1 | length 4
  Top Layer w0.254: v1(71.247,12.065) 72.009,12.827 R7_9.2
  Bottom Layer w0.254: v1(71.247,12.065) U1_9.1
NetR7_10_2: R7_10.2 U1_10.1 | length 4
  Top Layer w0.254: v1(84.201,12.065) 84.963,12.827 R7_10.2
  Bottom Layer w0.254: v1(84.201,12.065) U1_10.1
NetR8_1_2: R8_1.2 U1_1.15 | length 2.3
  Bottom Layer w0.254: U1_1.15 v2(-34.925,10.795)
NetR8_2_2: R8_2.2 U1_2.15 | length 2.3
  Bottom Layer w0.254: U1_2.15 v2(-21.971,10.795)
NetR8_3_2: R8_3.2 U1_3.15 | length 2.3
  Bottom Layer w0.254: U1_3.15 v2(-9.017,10.795)
NetR8_4_2: R8_4.2 U1_4.15 | length 2.3
  Bottom Layer w0.254: U1_4.15 v2(3.937,10.795)
NetR8_5_2: R8_5.2 U1_5.15 | length 2.3
  Bottom Layer w0.254: U1_5.15 v2(16.891,10.795)
NetR8_6_2: R8_6.2 U1_6.15 | length 4.5
  Bottom Layer w0.254: U1_6.15 v2(29.845,10.795) U1_6.15
NetR8_7_2: R8_7.2 U1_7.15 | length 2.3
  Bottom Layer w0.254: U1_7.15 v2(42.799,10.795)
NetR8_8_2: R8_8.2 U1_8.15 | length 2.3
  Bottom Layer w0.254: U1_8.15 v2(55.753,10.795)
NetR8_9_2: R8_9.2 U1_9.15 | length 2.3
  Bottom Layer w0.254: U1_9.15 v2(68.707,10.795)
NetR8_10_2: R8_10.2 U1_10.15 | length 2.3
  Bottom Layer w0.254: U1_10.15 v2(81.661,10.795)
NetU1_1_9: pad.9 U1_1.9 U1_2.14 | length 19.1
  Bottom Layer w0.254: U1_1.9 -32.639,3.175 -31.75,2.286 -29.337,2.286 -27.889,3.734 -27.889,8.509 -26.873,9.525 U1_2.14
NetU1_1_14: pad.4 U1_1.14 | length 5.7
  Bottom Layer w0.254: pad.4 -39.497,9.525 U1_1.14
NetU1_2_9: U1_2.9 U1_3.14 | length 18.5
  Bottom Layer w0.254: U1_2.9 -19.685,3.175 -18.796,2.286 -16.383,2.286 -14.357,4.312 -14.357,7.995 -12.827,9.525 U1_3.14
NetU1_3_9: U1_3.9 U1_4.14 | length 20.6
  Bottom Layer w0.254: U1_3.9 -6.731,3.175 -5.842,2.286 -3.429,2.286 -1.403,4.312 -1.403,7.995 ; U1_4.14 0.127,9.525 ; -1.403,7.995 0.127,9.525 ; -1.403,7.995 0.127,9.525
NetU1_4_9: U1_4.9 U1_5.14 | length 22.8
  Bottom Layer w0.254: U1_4.9 6.223,3.175 7.112,2.286 9.525,2.286 11.551,4.312 11.551,7.995 ; U1_5.14 13.081,9.525 ; 11.551,7.995 13.081,9.525 ; 11.551,7.995 13.081,9.525 ; 11.551,7.995 13.081,9.525
NetU1_5_9: U1_5.9 U1_6.14 | length 28.7
  Bottom Layer w0.254: U1_5.9 19.177,3.175 20.066,2.286 22.479,2.286 24.505,4.312 24.505,7.995 ; 24.505,7.995 26.035,9.525 ; 24.505,7.995 26.035,9.525 ; 24.505,7.995 26.035,9.525 ; 24.505,7.995 26.035,9.525 ; 24.505,7.995 26.035,9.525 ; 26.035,9.525 U1_6.14 26.035,9.525
NetU1_6_9: U1_6.9 U1_7.14 | length 39.7
  Bottom Layer w0.254: U1_7.14 38.989,9.525 ; 32.131,3.175 33.02,2.286 ; 32.131,3.175 U1_6.9 32.131,3.175 ; 32.131,3.175 33.02,2.286 ; 33.02,2.286 35.433,2.286 ; 33.02,2.286 35.433,2.286 ; 35.433,2.286 37.459,4.312 ; 35.433,2.286 37.459,4.312 ; 37.459,4.312 37.459,7.995 ; 37.459,4.312 37.459,7.995 ; 37.459,7.995 38.989,9.525 ; 37.459,7.995 38.989,9.525 ; 37.459,7.995 38.989,9.525 ; 37.459,7.995 38.989,9.525
NetU1_7_9: U1_7.9 U1_8.14 | length 22.8
  Bottom Layer w0.254: U1_7.9 45.085,3.175 45.974,2.286 48.387,2.286 50.413,4.312 50.413,7.995 ; U1_8.14 51.943,9.525 ; 50.413,7.995 51.943,9.525 ; 50.413,7.995 51.943,9.525 ; 50.413,7.995 51.943,9.525
NetU1_8_9: U1_8.9 U1_9.14 | length 25
  Bottom Layer w0.254: U1_8.9 58.039,3.175 58.928,2.286 61.341,2.286 63.367,4.312 63.367,7.995 ; U1_9.14 64.897,9.525 ; 63.367,7.995 64.897,9.525 ; 63.367,7.995 64.897,9.525 ; 63.367,7.995 64.897,9.525 ; 63.367,7.995 64.897,9.525
NetU1_9_9: U1_9.9 U1_10.14 | length 22.8
  Bottom Layer w0.254: U1_9.9 70.993,3.175 71.882,2.286 74.295,2.286 76.321,4.312 76.321,7.995 ; U1_10.14 77.851,9.525 ; 76.321,7.995 77.851,9.525 ; 76.321,7.995 77.851,9.525 ; 76.321,7.995 77.851,9.525
NetU1_10_9: U1_10.9
SHCP: pad.3 pad.11 U1_1.11 U1_2.11 U1_3.11 U1_4.11 U1_5.11 U1_6.11 U1_7.11 U1_8.11 U1_9.11 U1_10.11 | length 125.8
  Top Layer w0.254: v1(-34.671,5.715) -34.29,6.096 -26.543,6.096 v2(-25.984,5.537) ; v1(-21.717,5.715) -21.336,6.096 -13.208,6.096 v1(-12.827,5.715) ; v1(-8.763,5.715) -8.382,6.096 -0.254,6.096 v1(0.127,5.715) ; v1(4.191,5.715) 4.572,6.096 12.7,6.096 v1(13.081,5.715) ; v1(17.145,5.715) 17.526,6.096 25.654,6.096 v1(26.035,5.715) ; v1(30.099,5.715) 30.48,6.096 38.608,6.096 v1(38.989,5.715) ; v1(43.053,5.715) 43.434,6.096 51.562,6.096 v1(51.943,5.715) ; v1(56.007,5.715) 56.388,6.096 64.516,6.096 v1(64.897,5.715) ; v1(68.961,5.715) 69.342,6.096 77.47,6.096 v1(77.851,5.715)
  Bottom Layer w0.254: pad.3 -38.227,5.715 U1_1.11 v1(-34.671,5.715) ; v2(-25.984,5.537) -25.806,5.715 U1_2.11 v1(-21.717,5.715) ; v1(-12.827,5.715) U1_3.11 v1(-8.763,5.715) ; v1(0.127,5.715) U1_4.11 v1(4.191,5.715) ; v1(13.081,5.715) v1(17.145,5.715) ; v1(26.035,5.715) v1(30.099,5.715) ; v1(38.989,5.715) v1(43.053,5.715) ; v1(51.943,5.715) v1(56.007,5.715) ; v1(64.897,5.715) v1(68.961,5.715) ; v1(77.851,5.715) U1_10.11
STCP: pad.2 pad.10 U1_1.12 U1_2.12 U1_3.12 U1_4.12 U1_5.12 U1_6.12 U1_7.12 U1_8.12 U1_9.12 U1_10.12 | length 125.3
  Top Layer w0.254: v1(-34.671,6.985) -34.29,6.604 -26.162,6.604 -26.035,6.731 v2(-26.035,6.629) ; v1(-21.717,6.985) -21.336,6.604 -13.208,6.604 v1(-12.827,6.985) ; v1(-8.763,6.985) -8.382,6.604 -0.254,6.604 v1(0.127,6.985) ; v1(4.191,6.985) 4.572,6.604 12.7,6.604 v1(13.081,6.985) ; v1(17.145,6.985) 17.526,6.604 25.654,6.604 v1(26.035,6.985) ; v1(30.099,6.985) 30.48,6.604 38.608,6.604 v1(38.989,6.985) ; v1(43.053,6.985) 43.434,6.604 51.562,6.604 v1(51.943,6.985) ; v1(56.007,6.985) 56.388,6.604 64.516,6.604 v1(64.897,6.985) ; v1(68.961,6.985) 69.342,6.604 77.47,6.604 v1(77.851,6.985)
  Bottom Layer w0.254: pad.2 -39.497,6.985 U1_1.12 v1(-34.671,6.985) ; v2(-26.035,6.629) -25.679,6.985 U1_2.12 v1(-21.717,6.985) ; v1(-12.827,6.985) U1_3.12 v1(-8.763,6.985) ; v1(0.127,6.985) U1_4.12 v1(4.191,6.985) ; v1(13.081,6.985) v1(17.145,6.985) ; v1(26.035,6.985) v1(30.099,6.985) ; v1(38.989,6.985) v1(43.053,6.985) ; v1(51.943,6.985) v1(56.007,6.985) ; v1(64.897,6.985) v1(68.961,6.985) ; v1(77.851,6.985) U1_10.12

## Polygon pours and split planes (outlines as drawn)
GND on Bottom Layer "Bottom Layer-No Net" (solid, shelved, pour order 0): -43.18,17.78 91.592,17.78 91.592,-2.54 -43.18,-2.54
